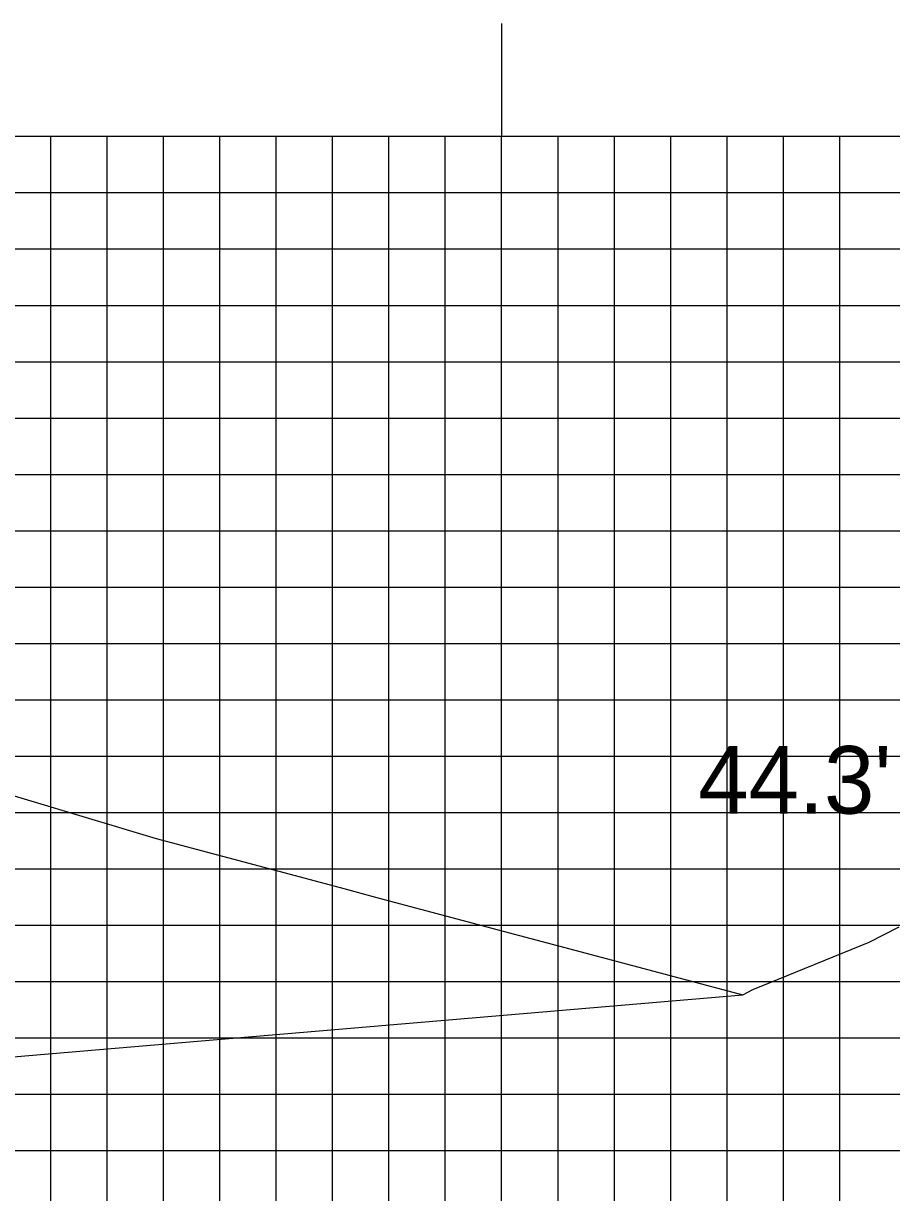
# Model space of a CAD drawing. Extents: x 1685192 to 1685536, y 461260 to 461480.
# Drawn here: x 1685389.74 to 1685405.15, y 461431.46 to 461452.21 of the extents above; entities that cross this region are included whole.
import ezdxf

# ---------------------------------------------------------------- set-up
doc = ezdxf.new("R2010")
doc.units = 0
for name, color, linetype in [('D_Roadway_SlopeLines', 7, 'Continuous'), ('D_Text_Standard', 7, 'Continuous'), ('MAJOR', 7, 'Continuous'), ('MINOR', 7, 'Continuous'), ('S_Roadway_Centerline', 7, 'Continuous')]:
    doc.layers.add(name, color=color, linetype=linetype)

msp = doc.modelspace()

# ---------------------------------------------------------------- linework, layer by layer
at = {"layer": 'D_Roadway_SlopeLines'}
msp.add_line((1685381.839, 461433.216), (1685402.509, 461434.97), dxfattribs=at)
at = {"layer": 'MAJOR'}
for p, q in [((1685398.229, 461452.21), (1685398.229, 461450.206)), ((1685218.229, 461450.206), (1685498.229, 461450.206)), ((1685218.229, 461450.206), (1685498.229, 461450.206)), ((1685398.229, 461425.206), (1685398.229, 461450.206)), ((1685218.229, 461445.206), (1685498.229, 461445.206)), ((1685218.229, 461440.206), (1685498.229, 461440.206)), ((1685218.229, 461435.206), (1685498.229, 461435.206))]:
    msp.add_line(p, q, dxfattribs=at)
at = {"layer": 'MINOR'}
for p, q in [((1685390.229, 461425.206), (1685390.229, 461450.206)), ((1685391.229, 461425.206), (1685391.229, 461450.206)), ((1685392.229, 461425.206), (1685392.229, 461450.206)), ((1685393.229, 461425.206), (1685393.229, 461450.206)), ((1685394.229, 461425.206), (1685394.229, 461450.206)), ((1685395.229, 461425.206), (1685395.229, 461450.206)), ((1685396.229, 461425.206), (1685396.229, 461450.206)), ((1685397.229, 461425.206), (1685397.229, 461450.206)), ((1685399.229, 461425.206), (1685399.229, 461450.206)), ((1685400.229, 461425.206), (1685400.229, 461450.206)), ((1685401.229, 461425.206), (1685401.229, 461450.206)), ((1685402.229, 461425.206), (1685402.229, 461450.206)), ((1685403.229, 461425.206), (1685403.229, 461450.206)), ((1685404.229, 461425.206), (1685404.229, 461450.206)), ((1685218.229, 461449.206), (1685498.229, 461449.206)), ((1685218.229, 461448.206), (1685498.229, 461448.206)), ((1685218.229, 461447.206), (1685498.229, 461447.206)), ((1685218.229, 461446.206), (1685498.229, 461446.206)), ((1685218.229, 461444.206), (1685498.229, 461444.206)), ((1685218.229, 461443.206), (1685498.229, 461443.206)), ((1685218.229, 461442.206), (1685498.229, 461442.206)), ((1685218.229, 461441.206), (1685498.229, 461441.206)), ((1685218.229, 461439.206), (1685498.229, 461439.206)), ((1685218.229, 461438.206), (1685498.229, 461438.206)), ((1685218.229, 461437.206), (1685498.229, 461437.206)), ((1685218.229, 461436.206), (1685498.229, 461436.206)), ((1685218.229, 461434.206), (1685498.229, 461434.206)), ((1685218.229, 461433.206), (1685498.229, 461433.206)), ((1685218.229, 461432.206), (1685498.229, 461432.206))]:
    msp.add_line(p, q, dxfattribs=at)
at = {"layer": 'S_Roadway_Centerline'}
msp.add_lwpolyline([(1685387.972, 461438.982), (1685388.109, 461438.941), (1685388.189, 461438.907), (1685388.354, 461438.861), (1685388.388, 461438.852), (1685388.55, 461438.807), (1685392.101, 461437.742), (1685395.366, 461436.873), (1685396.058, 461436.688), (1685398.256, 461436.103), (1685399.527, 461435.764), (1685402.509, 461434.97), (1685402.699, 461435.069), (1685402.802, 461435.111), (1685404.747, 461435.903), (1685405.282, 461436.177)], dxfattribs=at)

# ---------------------------------------------------------------- texts
at = {"layer": 'D_Text_Standard'}
msp.add_text("44.3'", height=1.2, dxfattribs=at).set_placement((1685401.718, 461438.185))

doc.saveas('drawing.dxf')
